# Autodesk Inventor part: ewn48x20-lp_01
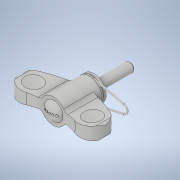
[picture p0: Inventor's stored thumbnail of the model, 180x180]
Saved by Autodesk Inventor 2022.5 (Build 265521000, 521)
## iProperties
Created: 2021-08
Part Number: ewn48x20-lp_01
Material: 一般
Document SubType Name: Modeling
Designer: ImaoCorp
Density: 1 g/cm^3
Appearance: 既定
Author: ImaoCorp
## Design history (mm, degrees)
feature "ewn48x20-lp_01"
node "ソリッド1"
